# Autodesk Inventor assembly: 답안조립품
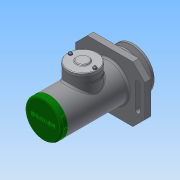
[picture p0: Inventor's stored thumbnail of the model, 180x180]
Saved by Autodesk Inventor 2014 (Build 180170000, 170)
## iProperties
Created: 2017-10
Part Number: 답안조립품
Document SubType Name: Assembly
Designer: net
Author: net
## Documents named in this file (20)
- C:\Users\net\Desktop\471007V1024\답안조립품.iam
- C:\Users\net\Desktop\471007V1024\본체.ipt
- C:\Users\net\Desktop\471007V1024\축.ipt
- C:\Users\net\Desktop\471007V1024\부시1.ipt
- C:\Users\net\Desktop\471007V1024\베어링 15 x 35 x 11.ipt
- C:\Users\net\Desktop\471007V1024\멈춤링 15 x 1.ipt
- C:\Users\net\Desktop\471007V1024\멈춤링 35x1.6.ipt
- C:\Users\net\Desktop\471007V1024\부시2.ipt
- C:\Users\net\Desktop\471007V1024\와셔 10x21.ipt
- C:\Users\net\Desktop\471007V1024\너트 M10.ipt
- C:\Users\net\Desktop\471007V1024\사이드 커버.ipt
- 사이드 커버.ipt
- C:\Users\net\Desktop\471007V1024\오일 실 15 25 7.ipt
- C:\Users\net\Desktop\471007V1024\키 4 x 4 x 18.ipt
- C:\Users\net\Desktop\471007V1024\V-벨트풀리.ipt
- C:\Users\net\Desktop\471007V1024\와셔 4x16.ipt
- C:\Users\net\Desktop\471007V1024\볼트 M4 x 10.ipt
- C:\Users\net\Desktop\471007V1024\탑 커버.ipt
- C:\Users\net\Desktop\471007V1024\와셔 3x6.ipt
- C:\Users\net\Desktop\471007V1024\십자볼트 M3 x 10.ipt
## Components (2 placed, 2 different names)
1. V-벨트풀리:1 — 각도:2
2. ISO 4017 M4 x 10:1
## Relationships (1: Angle 1)
- 각도:2 [Angle]: V-벨트풀리:1
